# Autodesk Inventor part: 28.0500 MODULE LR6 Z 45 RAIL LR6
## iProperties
Created: 2007-06
Part Number: 28.0500 MODULE LR6 Z 45 RAIL LR6
Material: Aluminum-6061
Document SubType Name: Modeling
Designer: Andy Moles
Density: 2.71 g/cm^3
Author: Andy Moles
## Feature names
1. Extrusion1
2. Hole1
3. Rectangular Pattern1
